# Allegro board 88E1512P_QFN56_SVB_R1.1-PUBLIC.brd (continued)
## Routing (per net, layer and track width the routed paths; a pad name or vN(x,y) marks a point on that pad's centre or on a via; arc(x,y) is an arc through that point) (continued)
U1_VDD_3.3V: length 101.9
  TOP w0.152: C194.1 v1(179.23,141.82) ; v1(148.35,91.44) 148.51,91.61 148.51,91.65 149.89,93.03 155.77,93.03 178.75,116.01 C22.1
  TOP w0.301: U1.36 148.1,91.69 v1(148.35,91.44)
  L3_PWR1 w0.914: 181.19,109.81 TP25.1 ; TP25.1 182.8,111.42 ; TP25.1 182.8,109.81 ; TP25.1 181.19,111.42
  BOTTOM w0.152: v1(179.23,141.82) 179.23,113.37 181.96,110.65
  BOTTOM w0.508: C47.1 v1(151.82,96.2) ; C46.1 v1(151.82,92.11) ; C195.1 181.96,110.65 TP25.1 C196.1 ; C50.1 v1(148.35,91.44) ; C48.1 v1(151.82,93.94) ; C49.1 v1(157.72,91.28)
  BOTTOM w2.032: L18.1 TP25.1
U1_VDDO: length 18.7
  TOP w0.3: U1.49 142.36,94.72 v1(142.54,94.54) ; U1.52 v1(140.86,94.51) ; v1(139.02,89.69) U1.11
  L3_PWR1 w0.914: 100.79,115.02 TP21.1 ; TP21.1 102.41,115.02 ; TP21.1 100.79,116.63 ; TP21.1 102.41,116.63
  BOTTOM w0.508: v1(140.86,94.51) 140.86,95.2 C18.1 ; v1(142.54,94.54) 142.93,94.93 C16.1 ; L13.1 99.6,116.28 C177.1 ; C21.1 139,89.67 v1(139.02,89.69) ; C17.1 v1(134.31,88.94) ; C20.1 v1(131.58,89.06) ; C176.1 TP21.1 ; C19.1 v1(140.83,109.48)
  BOTTOM w2.032: L13.1 TP21.1
U1_XTAL1: length 18.2
  TOP w0.301: U1.34 146.69,90.69 146.8,90.81 148.97,90.81 149.29,91.12 156.4,91.12 159.26,93.98 R3.1 R5.2
U1_XTAL2: length 17.7
  TOP w0.301: U1.33 151.62,90.19 152.43,89.38 162.12,89.38 R6.1
U2_1.8V: length 18.2
  L3_PWR1 w0.914: 78.44,49.61 JP33.1 ; JP33.1 80.05,49.61 ; JP33.1 78.44,51.22 ; JP33.1 80.05,51.22 ; 77.17,31.29 JP31.1 ; JP31.1 78.78,31.29 ; JP31.1 78.78,29.67 ; JP31.1 77.17,29.67 ; JP32.1 73.7,49.61 ; JP32.1 72.09,49.61 ; JP32.1 72.09,51.22 ; JP32.1 73.7,51.22 ; JP34.1 32.17,35.39 ; JP34.1 32.17,37 ; JP34.1 30.56,35.39 ; JP34.1 30.56,37
U2_AVDD_1.8V: length 23.5
  TOP w0.3: v1(55.67,92.69) U2.38 ; 54.85,88.16 v1(55.12,88.42)
  TOP w0.301: 54.85,88.16 54.83,88.13 U2.26 ; U2.19 51.33,88.22 v1(51.15,88.4) ; v1(59.88,93.5) 59.09,93.5 58.77,93.19 U2.39
  L4_PWR2 w0.914: 72.09,60.11 TP18.1 ; TP18.1 72.09,58.5 ; TP18.1 73.7,58.5 ; TP18.1 73.7,60.11
  BOTTOM w0.508: v1(55.67,92.69) 55.65,92.69 55.49,92.84 C81.1 ; C84.1 v1(53.69,77.21) ; v1(55.12,88.42) 55.78,88.42 C83.1 ; C80.1 v1(49.37,82.1) ; C82.1 v1(59.88,93.5) ; C87.1 50.53,87.79 v1(51.15,88.4) ; C86.1 v1(63.36,71.38) ; C171.1 TP18.1 ; C85.1 v1(72.63,82.71)
  BOTTOM w2.032: C170.1 TP18.1 L9.1
U2_AVDD_3.3V: length 18.1
  TOP w0.3: v1(54.17,88.4) 54.33,88.23 U2.25
  TOP w0.301: v1(52.1,88.39) 51.83,88.12 U2.20 51.83,86.63 v1(51.78,86.58) ; v1(54.39,86.58) 54.33,86.65 U2.25
  L3_PWR1 w0.914: TP28.1 31.67,65.62 ; TP28.1 31.67,67.23 ; TP28.1 30.06,65.62 ; TP28.1 30.06,67.23
  BOTTOM w0.508: v1(54.17,88.4) 54.46,88.11 C88.1 ; C91.1 v1(53.86,71.38) ; C208.1 TP28.1 C207.1 ; C90.1 54.37,86.56 v1(54.39,86.58) ; C89.1 51.81,88.1 v1(52.1,88.39) ; v1(51.78,86.58) 51.81,86.56 C92.1
  BOTTOM w2.032: L22.1 TP28.1
U2_AVDDC_1.8V: length 14.6
  TOP w0.3: U2.35 v1(55.65,91.19)
  L3_PWR1 w0.914: TP19.1 80.05,58.5 ; TP19.1 78.44,60.11 ; TP19.1 80.05,60.11 ; TP19.1 78.44,58.5
  BOTTOM w0.508: C78.1 v1(60.21,71.38) ; C77.1 v1(68.19,88.28) ; C76.1 v1(56.57,87.31) ; v1(55.65,91.19) 56.29,91.19 C79.1 ; C172.1 TP19.1
  BOTTOM w2.032: L10.1 TP19.1 C173.1
U2_AVDDF_1.8V: length 16.2
  TOP w0.3: U2.3 v1(49.56,93.69)
  TOP w0.301: U2.3 46.83,93.69 v1(46.82,93.68)
  L4_PWR2 w0.914: TP20.1 32.17,44.28 ; TP20.1 30.56,45.89 ; TP20.1 30.56,44.28 ; TP20.1 32.17,45.89
  BOTTOM w0.508: v1(49.56,93.69) 49.56,93.69 C72.1 ; C174.1 31.4,45.11 TP20.1 C175.1 ; C74.1 v1(47.99,99.43) ; v1(46.82,93.68) 46.2,93.68 C75.1 ; C73.1 v1(40.78,96.53)
  BOTTOM w2.032: L11.1 TP20.1
U2_CLK125: length 42.5
  TOP w0.152: U2.9 29.83,90.69 24.38,96.14 J10.1
  BOTTOM w0.152: C63.1 J10.1
U2_CONFIG: length 61.4
  TOP w0.152: U2.15 49.33,85.01 48.64,84.33 48.64,81.41 37.85,70.61 22.35,70.61 18.29,66.55 18.29,64.52 9.74,55.97 R150.1 7.62,53.85 JP58.1
U2_LED_0: length 68.8
  TOP w0.152: U2.14 46.66,88.19 45.47,87 42.74,87 34.99,79.25 v1(20.95,79.25)
  BOTTOM w0.152: v1(20.95,79.25) 16.38,74.68 16.38,53.09 15.75,52.45 14.22,52.45 12.95,53.72 JP13.5 12.57,52.96 13.84,51.69 R31.2
U2_LED_1: length 68.5
  TOP w0.152: JP13.3 16.38,52.45 21.46,52.45 JP54.1 R164.1 ; v1(32.38,81.28) 35.75,81.28 42.1,87.63 45.34,87.63 46.4,88.69 U2.13
  BOTTOM w0.152: JP54.1 24.38,52.83 24.38,60.71 20.32,64.77 20.32,70.36 31.24,81.28 v1(32.38,81.28)
U2_LED_2: length 57.6
  TOP w0.152: INTN_2.1 JP14.1 ; U2.12 46.04,89.19 45.28,88.42 41.47,88.42 36.61,83.57 v1(26.54,83.57)
  BOTTOM w0.152: INTN_2.1 19.3,61.98 19.3,75.31 26.54,82.55 v1(26.54,83.57)
U2_MDC: length 183.4
  TOP w0.152: v1(47.5,91.95) 47.76,91.69 U2.7 ; v1(138.81,112.52) 138.81,127.13 136.65,129.29 136.65,135.89 140.21,139.45 140.21,181.93 143.95,185.67 v1(145.45,185.67)
  BOTTOM w0.152: v1(47.5,91.95) 47.5,96.01 48.9,97.41 56.64,97.41 58.77,99.54 67.18,99.54 74.33,106.68 104.9,106.68 110.74,112.52 v1(138.81,112.52) ; v1(145.45,185.67) U4.6
U2_MDI_N_0: length 49
  TOP w0.127: R68.1 64.77,43.46 64.77,72.29 56.59,80.47 56.59,82.37 55.36,83.6 55.36,87.46 U2.27
U2_MDI_N_1: length 46.6
  TOP w0.127: U2.23 53.36,87.46 53.36,85.61 53.36,85.6 53.36,83.44 54.96,81.84 54.96,75.11 57.1,72.97 57.1,43.41 R73.1
U2_MDI_N_2: length 46.3
  TOP w0.127: R78.1 49.48,43.41 49.48,73.2 51.35,75.08 51.35,80.69 52.33,81.66 U2.21
U2_MDI_N_3: length 48.6
  TOP w0.127: R83.1 41.86,43.41 41.86,70.92 49.45,78.51 49.45,80.79 50.36,81.71 50.36,87.46 U2.17
U2_MDI_P_0: length 49
  TOP w0.127: R64.1 65.2,43.41 65.2,72.47 57.02,80.65 57.02,82.55 55.79,83.78 55.79,87.46 U2.28
U2_MDI_P_1: length 46.7
  TOP w0.127: R69.1 57.53,43.46 57.53,73.15 55.39,75.29 55.39,82.02 53.79,83.62 53.79,85.6 53.8,85.61 53.8,87.46 U2.24
U2_MDI_P_2: length 46.3
  TOP w0.127: U2.22 52.83,86.74 52.82,86.74 52.82,81.55 51.78,80.51 51.78,74.9 49.91,73.03 49.91,43.46 R74.1
U2_MDI_P_3: length 48.6
  TOP w0.127: U2.18 50.79,87.46 50.79,81.53 49.88,80.61 49.88,78.33 42.29,70.74 42.29,43.47 R80.2
U2_RESETN: length 137.7
  TOP w0.152: JP3.2 69.85,180.47 69.85,177.67 62.48,170.31 56.01,170.31 30.99,145.29 v1(30.99,129.79) ; v1(49.4,83.82) 49.83,84.24 U2.16
  BOTTOM w0.152: v1(30.99,129.79) 30.99,112.27 33.53,109.73 33.53,90.65 41.62,82.55 47.82,82.55 49.09,83.82 v1(49.4,83.82) ; R2.2 JP3.2
U2_RX_CLK: length 32.1
  TOP w0.152: v1(55.12,102.87) 54.33,102.08 U2.46 ; v1(55.12,106.68) 55.12,111.12 58.55,114.55 58.55,116.71 52.93,122.33 R139.1 R141.2
  BOTTOM w0.152: v1(55.12,106.68) v1(55.12,102.87)
U2_RX_CLK1: length 2.4
  TOP w0.152: R141.1 JP24.12
U2_RX_CTRL: length 33.8
  TOP w0.152: U2.43 55.83,99.9 60.96,105.03 60.96,108.46 69.6,117.09 JP24.2
U2_RXD_0: length 32.9
  TOP w0.152: JP24.4 67.06,116.59 59.94,109.47 59.94,105.16 55.33,100.54 U2.44
U2_RXD_1: length 32.1
  TOP w0.152: JP24.6 64.52,115.57 58.93,109.98 58.93,105.41 54.83,101.31 U2.45
U2_RXD_2: length 32.5
  TOP w0.152: U2.47 53.83,102.85 58.17,107.19 58.17,111 63.25,116.08 63.25,122.17 JP24.8
U2_RXD_3: length 32.6
  TOP w0.152: JP24.10 61.85,121.03 61.85,115.95 56.9,111 56.9,107.19 53.33,103.62 U2.48
U2_SIN_N: length 75.6
  TOP w0.127: C147.1 15.59,148.6 15.59,145.57 26.87,134.29 26.87,105.36 37.97,94.26 48.56,94.26 U2.2
U2_SIN_P: length 74.8
  TOP w0.127: U2.1 38.15,94.69 27.3,105.54 27.3,134.47 16.02,145.75 16.02,148.7 R98.2
U2_SOUT_N: length 45.3
  TOP w0.127: C154.2 15.35,113.53 15.35,109.77 32.46,92.66 48.6,92.66 U2.5
U2_SOUT_P: length 44.7
  TOP w0.127: R107.2 15.78,113.4 15.78,109.95 32.64,93.09 48.53,93.09 U2.4
U2_TX_CLK: length 40.6
  TOP w0.152: v1(50.99,100.95) 50.83,100.79 U2.53 ; R137.1 R143.2 35.47,124.88 JP53.11 37.85,124.71 37.85,114.68 47.5,105.03 v1(47.5,102.87)
  BOTTOM w0.152: v1(50.99,100.95) 50.98,100.96 49.41,100.96 v1(47.5,102.87)
U2_TX_CLK1: length 125.3
  TOP w0.152: R143.1 34.04,120.14 v1(36.83,117.35) ; v1(73.53,124.46) v1(73.53,120.65)
  BOTTOM w0.152: v1(36.83,117.35) 38.61,117.35 40.26,115.7 68.58,115.7 v1(73.53,120.65) ; JP23.12 140.84,130.43 137.41,127 116.97,127 112.65,131.32 91.95,131.32 87.63,127 76.07,127 v1(73.53,124.46)
U2_TX_CTRL: length 161.1
  TOP w0.152: U2.56 49.33,96.09 48.77,96.65 v1(48.77,102.87) ; v1(53.21,105.25) 53.21,110.49 54.99,112.27 54.99,117.09 50.55,121.54 50.55,124.71 JP53.1
  BOTTOM w0.152: JP23.2 153.54,124.59 152.78,123.83 115.44,123.83 111.12,128.14 94.23,128.14 89.92,123.83 72.14,123.83 68.2,119.89 53.59,119.89 52.7,120.78 52.7,126.11 51.82,127 49.66,127 49.28,126.62 JP53.1 ; v1(53.21,105.25) 52.9,104.93 50.83,104.93 v1(48.77,102.87)
U2_TXD_0: length 160.7
  TOP w0.152: v1(78.61,124.46) 78.61,122.87 v1(78.62,122.86) ; JP53.3 48.01,124.71 48.01,118.49 49.28,117.22 52.58,117.22 54.1,115.7 54.1,112.78 52.58,111.25 52.58,96.39 52.33,96.14 U2.50
  BOTTOM w0.152: JP23.4 151,125.6 149.86,124.46 115.8,124.46 111.48,128.78 93.85,128.78 89.53,124.46 v1(78.61,124.46) ; v1(78.62,122.86) 78.16,123.32 72.52,123.32 67.82,118.62 52.2,118.62 51.43,119.38 51.43,124.21 50.93,124.71 48.01,124.71 JP53.3
U2_TXD_1: length 159.9
  TOP w0.152: v1(77.34,124.46) v1(77.34,122.56) ; U2.51 51.83,114.92 50.55,116.2 47.12,116.2 45.47,117.86 45.47,124.71 JP53.5
  BOTTOM w0.152: JP23.6 148.46,127.64 145.92,125.09 116.2,125.09 111.89,129.41 93.47,129.41 89.15,125.09 77.98,125.09 v1(77.34,124.46) ; v1(77.34,122.56) 72.77,122.56 67.95,117.73 46.99,117.73 45.47,119.25 45.47,124.71 JP53.5
U2_TXD_2: length 161.2
  TOP w0.152: U2.54 50.33,96.87 50.04,97.16 50.04,99.69 50.04,112.4 47.88,114.55 43.81,114.55 42.93,115.44 42.93,124.71 JP53.7 ; v1(76.07,124.46) v1(76.07,121.92)
  BOTTOM w0.152: v1(76.07,124.46) 77.34,125.73 88.65,125.73 92.96,130.05 112.01,130.05 116.33,125.73 143,125.73 145.92,128.65 JP23.8 ; v1(76.07,121.92) 73.02,121.92 68.07,116.97 45.09,116.97 42.93,119.13 42.93,124.71 JP53.7
U2_TXD_3: length 162.6
  TOP w0.152: U2.55 49.83,96.48 49.4,96.9 49.4,108.59 47.62,110.36 43.56,110.36 40.39,113.54 40.39,124.71 JP53.9 ; v1(74.8,124.46) v1(74.8,121.29)
  BOTTOM w0.152: JP53.9 40.39,124.71 40.39,119.13 43.31,116.2 68.07,116.2 73.15,121.29 v1(74.8,121.29) ; JP23.10 143.38,129.41 140.34,126.37 116.71,126.37 112.39,130.68 92.58,130.68 88.27,126.37 76.71,126.37 v1(74.8,124.46)
U2_V18: length 24.7
  TOP w0.152: JP8.1 44.96,88.9 46.25,90.19 U2.10
  BOTTOM w0.152: R24.2 JP8.1
U2_VDD_1.0V: length 19.2
  TOP w0.3: U2.40 v1(55.65,93.69) ; U2.6 v1(49.46,92.19)
  TOP w0.301: v1(57.78,94.87) 57.61,94.69 U2.42
  TOP w2.032: L17.1 TP24.1
  L4_PWR2 w0.914: TP24.1 50.97,148.38 ; TP24.1 49.36,146.77 ; TP24.1 49.36,148.38 ; TP24.1 50.97,146.77
  BOTTOM w0.508: C64.1 55.81,93.53 v1(55.65,93.69) ; C58.1 49.44,92.21 v1(49.46,92.19) ; C60.1 v1(45.34,108.48) ; C62.1 v1(73.27,104.09) ; C191.1 TP24.1 50.14,147.6 C193.1 ; C61.1 v1(68.19,98.58) ; C59.1 v1(57.78,94.87)
U2_VDD_3.3V: length 17.9
  TOP w0.301: U2.36 59.56,91.69 v1(59.82,91.95)
  L3_PWR1 w0.914: 74.51,110.19 TP26.1 ; TP26.1 74.51,111.8 ; TP26.1 76.12,110.19 ; TP26.1 76.12,111.8
  BOTTOM w0.508: C95.1 v1(64.19,92.43) ; C197.1 77.19,110.8 L19.1 ; C96.1 v1(68.19,92.87) ; C93.1 v1(59.82,91.95) ; C198.1 TP26.1 ; C97.1 v1(64.19,95.85) ; C94.1 v1(61.02,95.85)
  BOTTOM w2.032: L19.1 TP26.1
U2_VDDO: length 17.6
  TOP w0.3: v1(49.51,89.69) U2.11
  TOP w0.301: U2.49 v1(52.83,94.51) ; U2.52 v1(51.33,94.51)
  L3_PWR1 w0.914: TP22.1 29.76,107.49 ; TP22.1 28.15,105.87 ; TP22.1 29.76,105.87 ; TP22.1 28.15,107.49
  BOTTOM w0.508: v1(52.83,94.51) 52.92,94.6 C65.1 ; C66.1 51.28,94.55 v1(51.33,94.51) ; C68.1 v1(42.93,108.43) ; C70.1 v1(44.8,89.69) ; C67.1 49.38,89.56 v1(49.51,89.69) ; C69.1 v1(39.98,89.86) ; C184.1 TP22.1
  BOTTOM w2.032: C182.1 TP22.1 L14.1
U2_XTAL1: length 16.9
  TOP w0.301: U2.34 57.28,90.69 57.63,91.04
  TOP w0.381: 57.63,91.04 72.97,91.04 R17.1
U2_XTAL2: length 18.3
  TOP w0.301: 62.73,90.19 U2.33
  TOP w0.508: 62.73,90.19 63.26,89.66 64.14,89.66 68.71,85.09 R21.1
N16787604: length 2.8
  TOP w0.152: D3.2 96.04,33.26 v1(96.04,34.29)
  BOTTOM w0.152: R30.1 97.15,35.4 v1(96.04,34.29)
N16796830: length 9.3
  TOP w0.152: 181.86,101.98 181.68,101.79 Y1.1
N16796833: length 5.4
  TOP w0.152: Y1.3 164.93,97.6 R4.1
N16796834: length 31.5
  TOP w0.152: R3.2 176.4,93.98 179.71,97.28 183.26,97.28 186.94,100.97 J1.1
  BOTTOM w0.508: C3.1 J1.1
N16796839: length 5.9
  TOP w0.152: C6.1 167.3,92.11 Y2.2 166.69,92.39 R5.1
N16994346: length 40.2
  TOP w0.127: U1.32 146.1,89.66 150.5,89.66 152.05,88.11 155.74,88.11 170.31,73.53 176.43,73.53 v1(177.19,74.29) R10.2
  BOTTOM w0.127: v1(177.19,74.29) 177.03,74.14 R14.1
N16994348: length 40.2
  TOP w0.127: R12.2 v1(177.2,72.39) 176.49,73.1 170.14,73.1 170.01,73.23 155.56,87.67 151.87,87.67 150.32,89.22 146.1,89.22 U1.31
  BOTTOM w0.127: v1(177.2,72.39) 177.04,72.55 R15.1
N17016825: length 19.6
  TOP w0.152: J8.1 87.88,89.66 85.47,92.08 76.08,92.08 R17.2
  BOTTOM w0.508: C54.1 J8.1
N17016957: length 4.5
  TOP w0.152: Y3.3 76.07,95.57 73.69,93.19 73.69,92.87 R18.1
N17016970: length 6.7
  TOP w0.381: Y4.2 74.17,88.27 73.22,89.21 R19.1
  BOTTOM w0.508: Y4.2 78.14,88.43 C55.1
N17016978: length 5.2
  TOP w0.381: R21.2 v1(76.71,85.09)
  BOTTOM w0.381: v1(76.71,85.09) 77.65,85.09 C56.1
  BOTTOM w0.508: R20.1 79.26,84.93 C56.1
N17193751: length 4.8
  TOP w0.152: JP2.3 63.82,184.97 U3.2
N17251537: length 10.2
  TOP w0.152: JP58.2 JP13.8 JP13.6 JP13.4 JP13.2
N17251820: length 3.6
  TOP w0.152: v1(17.97,47.84) 17.02,46.89 D6.2
  BOTTOM w0.152: R33.1 v1(17.97,47.84)
N17493866: length 3.8
  TOP w0.127: JP5.2 181.64,73.18 180.54,73.18 R12.1
N17495532: length 3.7
  TOP w0.127: R11.1 180.38,73.66 181.8,73.66 JP5.1
N17503153: length 3.8
  TOP w0.152: JP7.1 81.03,100.02 Y3.1
N17787307: length 6.3
  TOP w0.152: JP2.2 JP3.1 JP3.3
N17830081: length 10.2
  TOP w0.152: JP57.2 JP11.8 JP11.6 JP11.4 JP11.2
N17893687: length 20.7
  TOP w0.127: U6.11 56.07,26.43 56.07,26.65 55.12,27.6 55.12,29.21 62.92,37.01 62.92,37.03 65.18,39.29 65.18,40.37 R65.1
N17893693: length 20.5
  TOP w0.127: R67.1 64.74,40.37 64.74,39.47 62.49,37.21 62.49,37.19 54.69,29.39 54.69,27.42 55.44,26.67 55.44,26.17 U6.10
N17893695: length 23
  TOP w0.127: R70.1 58.29,41.17 58.06,41.4 57.91,41.4 57.56,41.05 57.56,34.66 53.59,30.7 53.59,24.8 53.61,24.79 53.61,24.69
  TOP w0.152: U6.4 54.18,22.73 54.61,22.73 54.86,22.99 54.86,24.32 54.74,24.45 53.85,24.45 53.61,24.69
N17893699: length 20.1
  TOP w0.127: U6.3 51.31,23.57 51.31,23.97 52.45,25.11 52.45,36.83 49.94,39.34 49.94,40.38 50.67,41.11 R75.1
N17893703: length 20.3
  TOP w0.127: R77.1 49.5,40.37 49.5,39.17 52.02,36.65 52.02,25.29 50.88,24.15 50.87,24.15 U6.2
N17893707: length 22.5
  TOP w0.127: R80.1 43.05,41.11 42.32,40.38 42.32,38.46 49.43,31.34 49.43,29.74
  TOP w0.152: U6.8 48.51,25.86 48.51,26.54 48.8,26.83 50.83,26.83 51.18,27.18 51.18,28.96 50.77,29.37 49.8,29.37 49.43,29.74
N17893711: length 23.6
  TOP w0.127: R82.1 41.88,40.37 41.88,38.28 49,31.16 49,29.76
  TOP w0.152: U6.9 49.71,24.51 48.26,24.51 47.75,25.02 47.75,26.83 47.97,27.05 47.97,28.74 48.13,28.89 48.13,28.89 49,29.76
N18175709: length 24.2
  TOP w0.127: R72.1 57.12,40.37 57.12,34.84 53.16,30.88 53.16,24.61
  TOP w0.152: U6.5 54.88,22.07 53.37,22.07 52.87,22.57 52.87,24.31 53.16,24.61
N18237123: length 4.4
  TOP w0.152: U1.30 v1(149.52,88.69)
  BOTTOM w0.152: R13.1 149.47,88.75 v1(149.52,88.69)
N18290180: length 8.4
  BOTTOM w0.127: R48.2 139.45,47.5 139.45,49.38 138.06,50.76 137.33,50.76 137.03,51.05 JP17.1 136.56,51.35 R50.1
N18290184: length 7.7
  BOTTOM w0.127: R53.2 139.01,47.61 139.01,49.2 137.88,50.33 137.33,50.33 137.03,50.04 JP17.2 136.56,49.75 R50.2
N18290198: length 10.7
  BOTTOM w0.127: U5.2 136.27,36.93 136.69,37.34 136.69,40.28 135.43,41.54 133.5,41.54 132.59,42.45 132.59,43.08 R57.1
N18290204: length 10.7
  BOTTOM w0.127: U5.3 137.54,36.86 137.12,37.28 137.12,40.46 135.6,41.97 133.67,41.97 133.02,42.63 133.02,43.03 R55.1
N18290208: length 8.5
  BOTTOM w0.127: R51.1 138.94,43.08 138.94,42.16 140.5,40.59 140.5,37.31 140.08,36.89 U5.5
N18290216: length 8.6
  BOTTOM w0.127: R49.1 139.37,43.03 139.37,42.34 140.93,40.77 140.93,37.28 141.35,36.86 141.35,36.26
N18290228: length 8.3
  BOTTOM w0.127: U5.8 143.89,36.89 144.31,37.31 144.31,41.29 145.33,42.31 145.33,43.03 R45.1
N18290246: length 8.4
  BOTTOM w0.127: R56.1 130.21,51.35 JP18.1 130.68,51.05 130.98,50.76 131.71,50.76 133.1,49.38 133.1,47.5 R54.2
N18290250: length 7.7
  BOTTOM w0.127: R56.2 130.21,49.75 JP18.2 130.68,50.04 130.98,50.33 131.53,50.33 132.66,49.2 132.66,47.61 R59.2
N18290323: length 8.3
  BOTTOM w0.127: U5.9 145.16,36.86 144.74,37.28 144.74,41.11 145.76,42.13 145.76,43.08 R43.1
N18290640: length 8.3
  BOTTOM w0.127: R37.1 149.26,51.35 JP15.1 149.73,51.02 150.05,50.7 150.66,50.7 152.15,49.22 152.15,47.5 R40.2
N18290658: length 7.5
  BOTTOM w0.127: R42.2 151.71,47.61 151.71,49.04 150.48,50.27 150.09,50.27 149.73,49.91 JP15.2 149.26,49.75 R37.2
N18290664: length 8.5
  BOTTOM w0.127: 146.51,15.42 148.12,17.03 148.12,21.23 U5.14
  BOTTOM w0.152: 145.29,15.88 145.74,15.42 146.51,15.42
N18290670: length 9.3
  BOTTOM w0.127: 148.97,21.65 148.55,21.23 148.55,16.85 146.56,14.86
  BOTTOM w0.152: 146.56,14.86 CON1.1
N18290676: length 9.1
  TOP w0.127: v1(145.13,18.16) 144.81,17.84 144.81,17.18 144.02,16.38
  TOP w0.152: CON1.3 144.02,16.38
  BOTTOM w0.127: U5.16 144.81,21.3 144.81,18.48 v1(145.13,18.16)
N18290682: length 9.5
  TOP w0.127: v1(144.02,18.16) 144.38,17.8 144.38,17.36 143.98,16.95
  TOP w0.152: 140.21,15.88 141.29,16.95 143.98,16.95
  BOTTOM w0.127: v1(144.02,18.16) 144.34,18.48 144.34,21.21 U5.17
N18290688: length 9.3
  BOTTOM w0.127: 141.95,14.64 141.75,14.84 141.75,18.78 140.97,19.56 140.97,21.27 141.35,21.65
  BOTTOM w0.152: 142.75,15.88 142.75,15.11 142.27,14.64 141.95,14.64
N18290694: length 8.9
  BOTTOM w0.127: 141.48,14.48 141.32,14.64 141.32,18.6 140.54,19.38 140.54,21.2 U5.20
  BOTTOM w0.152: 141.48,14.48 CON1.5
N18290700: length 9.5
  BOTTOM w0.127: 138.94,14.32 138.94,14.48 139.19,14.73 139.19,17.78 137.12,19.85 137.12,21.23 U5.22
  BOTTOM w0.152: CON1.7 138.94,14.32
N18290706: length 10
  BOTTOM w0.127: U5.23 136.69,21.23 136.69,19.67 138.76,17.6 138.76,14.91 138.49,14.64
  BOTTOM w0.152: 138.49,14.64 137.99,14.64 137.67,14.95 137.67,15.88
N18290712: length 1.8
  BOTTOM w0.762: C105.1 R38.1
N18290718: length 20.7
  TOP w0.762: R52.2 124.19,22.12 C118.1
  BOTTOM w0.762: R52.2 127.51,25.15 136.78,25.15 138.81,23.11 U5.21
N18290720: length 10.5
  TOP w0.762: C120.1 128.29,22.12 R58.2
  BOTTOM w0.762: R58.2 129.29,23.11 133.54,23.11 U5.24
N18290726: length 14.7
  TOP w0.762: R38.2 153.69,21.97 C100.1
  BOTTOM w0.762: U5.15 146.43,22.86 147.45,23.88 154.18,23.88 R38.2
N18290728: length 1.8
  BOTTOM w0.762: C109.1 R46.1
N18290732: length 1.8
  BOTTOM w0.762: C113.1 R52.1
N18290736: length 24.1
  TOP w0.762: R46.2 162.29,21.97 C98.1
  BOTTOM w0.762: U5.18 142.62,23.24 145.16,25.78 156.08,25.78 R46.2
N18290738: length 1.8
  BOTTOM w0.762: C117.1 R58.1
N18290828: length 9.4
  BOTTOM w0.127: R36.1 152.07,43.03 152.07,41.61 148.55,38.09 148.55,37.28 148.97,36.86 148.97,36.26
N18290888: length 8.4
  BOTTOM w0.127: R39.2 146.09,47.21 146.08,47.21 145.74,47.55 145.74,49.43 144.41,50.76 143.7,50.76 143.38,51.08 JP16.1 142.91,51.35 R44.1
N18290892: length 7.6
  BOTTOM w0.127: R44.2 142.91,49.75 JP16.2 143.38,49.91 143.8,50.33 144.23,50.33 145.31,49.25 145.31,47.56 R47.2
N18290908: length 9.3
  BOTTOM w0.127: U5.11 147.7,36.89 148.12,37.31 148.12,38.27 151.64,41.79 151.64,43.08 R41.1
N18307922: length 12.1
  TOP w0.127: R64.2 v1(67.51,43.65)
  BOTTOM w0.127: R66.1 61,48.42 JP19.1 62.52,47.84 63.29,47.84 65.12,46.01 65.12,43.97
  BOTTOM w0.152: 65.12,43.97 65.44,43.65 v1(67.51,43.65)
N18307926: length 11.3
  TOP w0.127: R68.2 v1(62.41,43.65)
  BOTTOM w0.127: R66.2 61,46.83 JP19.2 62.52,47.41 63.11,47.41 64.69,45.83 64.69,44.02
  BOTTOM w0.152: v1(62.41,43.65) 64.32,43.65 64.69,44.02
N18317435: length 12.1
  TOP w0.127: R69.2 v1(59.89,43.65)
  BOTTOM w0.127: 57.5,43.97 57.5,46.01 55.67,47.84 54.9,47.84 JP20.1 53.38,48.42 R71.1
  BOTTOM w0.152: 57.5,43.97 57.82,43.65 v1(59.89,43.65)
N18317437: length 11.3
  TOP w0.127: R73.2 v1(54.79,43.65)
  BOTTOM w0.127: R71.2 53.38,46.83 JP20.2 54.9,47.41 55.49,47.41 57.07,45.83 57.07,44.02
  BOTTOM w0.152: v1(54.79,43.65) 56.7,43.65 57.07,44.02
N18317956: length 12.1
  TOP w0.127: R74.2 v1(52.27,43.65)
  BOTTOM w0.127: R76.1 45.76,48.42 JP21.1 47.28,47.84 48.05,47.84 49.88,46.01 49.88,43.97
  BOTTOM w0.152: 49.88,43.97 50.2,43.65 v1(52.27,43.65)
N18317958: length 11.3
  TOP w0.127: R78.2 v1(47.17,43.65)
  BOTTOM w0.127: R76.2 45.76,46.83 JP21.2 47.28,47.41 47.87,47.41 49.45,45.83 49.45,44.02
  BOTTOM w0.152: v1(47.17,43.65) 49.08,43.65 49.45,44.02
N18318493: length 12.1
  TOP w0.152: R79.2 v1(44.65,43.65)
  BOTTOM w0.127: R81.1 38.14,48.42 JP22.1 39.66,47.84 40.43,47.84 42.26,46.01 42.26,43.97
  BOTTOM w0.152: 42.26,43.97 42.58,43.65 v1(44.65,43.65)
N18318495: length 11.3
  TOP w0.152: R83.2 v1(39.55,43.65)
  BOTTOM w0.127: 41.83,44.02 41.83,45.83 40.25,47.41 39.66,47.41 JP22.2 38.14,46.83 R81.2
  BOTTOM w0.152: v1(39.55,43.65) 41.46,43.65 41.83,44.02
N18570142: length 2.3
  BOTTOM w0.152: JP12.2 97.16,37.47 R30.2
N18601588: length 51.7
  TOP w0.152: U1.29 146.1,88.16 149.46,88.16 150.88,86.74 153.42,86.74 167.64,72.52 167.64,57.66 JP6.1
N18793953: length 5.5
  TOP w0.152: C7.1 167.14,86.86 Y2.1 167.09,86.83 R6.2
N19074906: length 29.6
  TOP w0.152: JP10.1 72.9,75.18 72.9,76.36 61.47,87.79 58.13,87.79 57.73,88.19 U2.29
N19074920: length 4.6
  TOP w0.152: v1(60.04,88.69) U2.30
  BOTTOM w0.152: v1(60.04,88.69) 59.98,88.75 R25.1
N19074934: length 29.1
  TOP w0.127: U2.31 56.56,89.22 61.4,89.22 75.02,75.6 76.92,75.6 77.98,74.55
  BOTTOM w0.127: R27.1 77.98,74.55
N19074982: length 29.1
  TOP w0.127: U2.32 56.56,89.66 61.58,89.66 75.2,76.03 76.92,76.03 JP9.2
  BOTTOM w0.127: R26.1 JP9.2
N19224300: length 22.8
  L4_PWR2 w0.914: 169.25,162.39 JP49.2 ; JP49.2 170.86,162.39 ; JP49.2 169.25,164 ; JP49.2 170.86,164 ; 83.4,110.19 JP48.1 ; JP48.1 85.01,110.19 ; JP48.1 83.4,111.8 ; JP48.1 85.01,111.8 ; JP52.1 22.78,67.23 ; JP52.1 21.17,65.62 ; JP52.1 22.78,65.62 ; JP52.1 21.17,67.23 ; JP47.1 191.69,109.81 ; JP47.1 190.08,111.42 ; JP47.1 190.08,109.81 ; JP47.1 191.69,111.42 ; JP50.1 90.34,62.06 ; JP50.1 88.73,62.06 ; JP50.1 90.34,63.67 ; JP50.1 88.73,63.67
N19224537: length 2.3
  BOTTOM w2.032: L21.2 JP50.2
N19224649: length 6.2
  TOP w0.254: C201.1 179.91,175.78 U12.9 178.68,175.78 178.38,176.08 178.38,176.38 177.48,177.28 U12.1
  TOP w0.508: R135.2 181.19,176.08 C201.1
N19224675: length 1.5
  TOP w0.152: R126.1 113.32,179.32 U11.14
N19224683: length 6.2
  TOP w0.254: U11.1 115.33,178.05 115.85,178.57 115.85,179.5 116.12,179.78 116.51,179.78 116.83,180.1 U11.9 116.83,181.31 C189.1
  TOP w0.508: C189.1 116.53,182.58 R130.2
N19224747: length 3.6
  TOP w0.152: R128.1 112.42,178.44 113.86,178.44 114.24,178.82 U11.15
N19224753: length 3.6
  TOP w2.032: L15.2 JP43.2
N19224758: length 13.7
  L3_PWR1 w0.914: JP44.2 126.41,167.47 ; JP44.2 124.8,169.08 ; JP44.2 126.41,169.08 ; JP44.2 124.8,167.47 ; JP45.1 50.97,156.93 ; JP45.1 50.97,158.54 ; JP45.1 49.36,156.93 ; JP45.1 49.36,158.54 ; JP43.1 137.08,165.56 ; JP43.1 135.47,165.56 ; JP43.1 135.47,167.18 ; JP43.1 137.08,167.18
N19224792: length 1.7
  TOP w0.508: D11.1 R131.2
N19224808: length 1.5
  TOP w0.152: U12.14 177.92,179.29 R132.2
N19224958: length 1.7
  BOTTOM w2.032: L22.2 JP52.2
N19224996: length 3.6
  TOP w0.152: U12.15 177.42,178.37 177.04,178.75 177.04,180.19 R133.1
N19225038: length 2.3
  TOP w2.032: L17.2 JP45.2
N19225131: length 1.8
  TOP w0.152: D10.1 R125.2
N19227820: length 13.5
  L3_PWR1 w0.914: JP41.1 29.76,116.38 ; JP41.1 28.15,116.38 ; JP41.1 29.76,114.76 ; JP41.1 28.15,114.76 ; 142.58,167.18 JP39.2 ; JP39.2 142.58,165.56 ; JP39.2 143.38,167.44 ; JP39.2 143.38,165.3 ; 92.16,116.63 JP40.1 ; JP40.1 93.77,115.02 ; JP40.1 93.77,116.63 ; JP40.1 92.16,115.02
N19228113: length 1.7
  BOTTOM w2.032: L6.2 JP26.2
N19228203: length 1.5
  TOP w0.152: U9.14 18.81,19.93 R113.2
N19228291: length 6.6
  TOP w0.152: C167.1 16.07,23.14
  TOP w0.254: C167.1 17.02,23.14 17.32,23.44 U9.9 18.12,23.44 18.36,23.19 18.36,22.89 19.31,21.94 U9.1
  TOP w0.381: C167.1 15.55,23.14 R116.2
N19228315: length 1.7
  BOTTOM w2.032: L5.2 JP25.2
N19228347: length 10.4
  TOP w0.254: U9.3 20.94,22.94 21.15,22.73 21.15,22.73 v1(21.62,22.26)
  BOTTOM w0.508: v1(25.91,27.18) 25.91,25.75 22.41,22.26 v1(21.62,22.26) ; R112.1 JP29.2
N19228371: length 23.7
  TOP w0.152: v1(157.67,176.85) 157.67,176.69 157.6,176.62 U10.14
  BOTTOM w0.508: v1(157.67,176.85) 160.53,176.85 163.39,179.7 163.39,185.1 JP35.2 JP36.2 JP37.2 JP38.2
N19228441: length 1.7
  TOP w0.508: D8.1 R110.2
N19228445: length 1.7
  TOP w0.152: D9.1 v1(160.21,163.83)
  BOTTOM w0.152: R117.2 v1(160.21,163.83)
N19228523: length 3.6
  TOP w0.152: U9.15 19.31,20.85 19.7,20.46 19.7,19.03 R114.1
N19228594: length 1.7
  BOTTOM w2.032: L8.2 JP28.2
N19228794: length 1.7
  BOTTOM w2.032: L14.2 JP41.2
N19228818: length 1.5
  BOTTOM w2.032: L13.2 JP40.2
N19228838: length 6.2
  TOP w0.254: C180.1 159.59,173.24 U10.9 158.36,173.24 158.06,173.54 158.06,173.84 157.16,174.74 U10.1
  TOP w0.508: C180.1 160.87,173.54 R123.2
N19228887: length 3.6
  TOP w0.152: R118.1 156.72,177.65 156.72,176.21 157.1,175.83 U10.15
N19228961: length 13.7
  L4_PWR2 w0.914: JP27.2 125.52,29.76 ; JP27.2 123.91,29.76 ; JP27.2 125.52,28.15 ; JP27.2 123.91,28.15 ; 29.55,28.28 JP29.1 ; JP29.1 29.55,29.89 ; JP29.1 31.16,28.28 ; JP29.1 31.16,29.89 ; JP31.2 78.78,28.75 ; JP31.2 78.78,27.13 ; JP31.2 77.17,28.75 ; JP31.2 77.17,27.13
N19229117: length 1.7
  BOTTOM w2.032: L10.2 79.25,52.96
N19229193: length 1.7
  BOTTOM w2.032: L9.2 72.9,52.96
N19229239: length 1.7
  BOTTOM w2.032: L11.2 JP34.2
N19229269: length 1.7
  BOTTOM w0.508: R120.1 JP36.1
N19229277: length 22
  TOP w2.54: F1.1 J20.1 J20.2
  BOTTOM w0.508: C159.1 J20.1
  BOTTOM w1.016: C160.1 163.96,200.45 J20.2
N19229287: length 2.6
  TOP w0.508: D7.1 152.53,197.4 v1(152.53,196.06)
  BOTTOM w0.508: R111.1 v1(152.53,196.06)
N19241861: length 4.4
  TOP w0.508: U7.15 v1(88.57,168.81)
  BOTTOM w0.508: C142.1 88.57,169.43 v1(88.57,168.81) 88.57,168.23 88.05,167.71 L2.1
N19242097: length 16.9
  TOP w0.152: C145.1 79.09,156.84 79.09,161.77 77.03,163.83 J14.1
N19242099: length 16.8
  TOP w0.152: J13.1 64.01,163.83 67.18,160.66 67.18,156.36 C144.1
N19242143: length 6.7
  TOP w0.508: U7.16 v1(89.37,168.81)
  BOTTOM w0.508: C138.1 89.72,171.73 C139.1 89.37,169.52 v1(89.37,168.81) 89.37,168.24 89.81,167.8 L1.2
N19242271: length 9.2
  TOP w0.152: C136.2 98.3,150.81 J11.1
N19242275: length 10.1
  TOP w0.152: J12.1 85.6,152.87 C137.2
N19242333: length 31.7
  TOP w0.127: U7.18 91.16,167.17 91.16,163.35 91.95,162.56 92.88,162.56 v1(93.22,162.22) ; R94.1 73.53,155.42 v1(73.53,155.89)
  BOTTOM w0.127: v1(73.53,155.89) 73.17,156.25 73.17,157.28 75.91,160.02 88.11,160.02 90.65,162.56 92.88,162.56 v1(93.22,162.22)
N19242335: length 31.8
  TOP w0.127: R95.1 72.27,155.43 72.27,155.79 72.18,155.88 v1(72.18,155.88) ; v1(93.22,163.33) 92.88,162.99 92.13,162.99 91.59,163.53 91.59,167.17 U7.19
  BOTTOM w0.127: v1(93.22,163.33) 92.88,162.99 90.47,162.99 87.93,160.45 75.74,160.45 72.74,157.46 72.74,156.44 v1(72.18,155.88)
N19242343: length 20.7
  TOP w0.127: U7.13 86.76,167.13 86.76,164.55 93.2,158.11 93.2,150.52 94.01,149.71 R85.1
N19242345: length 20.7
  TOP w0.127: R86.1 92.76,150.52 92.76,157.93 86.32,164.37 86.32,167.2 U7.12
N19242395: length 2.9
  TOP w0.152: U7.6 v1(88.17,177.01)
  BOTTOM w0.152: R89.1 87.82,177.64 87.82,177.36 v1(88.17,177.01)
N19242397: length 2.6
  TOP w0.152: U7.5 v1(88.97,177.01)
  BOTTOM w0.152: R90.1 88.97,178.07 v1(88.97,177.01)
N19242401: length 2.9
  TOP w0.152: U7.4 v1(89.77,177.01)
  BOTTOM w0.152: R91.1 90.04,177.64 90.04,177.28 v1(89.77,177.01)
N19242403: length 2.9
  TOP w0.152: U7.2 v1(91.37,177.07)
  BOTTOM w0.152: R92.1 92.1,178.11 91.63,177.64 91.63,177.32 v1(91.37,177.07)
N19242417: length 3
  TOP w0.152: U7.8 v1(86.57,177.01)
  BOTTOM w0.152: v1(86.57,177.01) 86.39,177.19 86.39,177.64 85.92,178.11 R88.1
N19251259: length 4.6
  TOP w0.508: U8.15 v1(30.15,168.81)
  BOTTOM w0.508: L4.1 29.63,167.8 30.15,168.32 v1(30.15,168.81) 30.15,169.59 C152.1
N19251492: length 8.2
  TOP w0.152: C155.1 21.97,118.01 J18.1
N19251494: length 8.2
  TOP w0.152: J17.1 9.27,118.01 12.92,114.37 C154.1
N19251531: length 6.7
  TOP w0.508: U8.16 v1(30.95,168.81)
  BOTTOM w0.508: C148.1 31.46,172.05 C149.1 31.38,170.02 30.95,169.59 v1(30.95,168.81) 30.95,168.27 31.39,167.83 L3.2
N19251660: length 8.2
  TOP w0.152: C146.2 22.1,153.19 J15.1
N19251670: length 8.1
  TOP w0.152: C147.2 9.4,153.51 J16.1
N19251724: length 70.6
  TOP w0.127: v1(32.44,163.47) 32.74,163.76 32.74,166.37 32.55,166.55 U8.18 ; R107.1 15.84,116.85 15.84,142.02 12.17,145.69 11.16,145.69 v1(10.83,146.02)
  BOTTOM w0.127: v1(10.83,146.02) 11.16,145.69 11.76,145.69 12.57,146.5 12.57,151.76 22.53,161.72 32.24,161.72 32.78,162.26 32.78,163.13 v1(32.44,163.47)
N19251726: length 70.7
  TOP w0.127: v1(10.83,144.92) 11.16,145.26 11.99,145.26 15.41,141.85 15.41,116.69 14.67,115.96 R108.1 ; U8.19 33.35,166.71 33.17,166.53 33.17,163.85 v1(33.55,163.47)
  BOTTOM w0.127: v1(33.55,163.47) 33.21,163.13 33.21,162.08 32.42,161.29 22.71,161.29 13,151.59 13,146.32 11.94,145.26 11.16,145.26 v1(10.83,144.92)
N19251738: length 25.5
  TOP w0.127: R98.1 15.96,152.03 15.96,158.17 19.4,161.61 25.75,161.61 28.37,164.23 28.37,166.53 28.55,166.71 U8.13
N19251740: length 25.5
  TOP w0.127: R99.1 15.53,152.03 15.53,158.35 19.22,162.04 25.57,162.04 27.94,164.41 27.94,166.53 27.75,166.71 U8.12
N19251790: length 2.9
  TOP w0.152: U8.6 v1(29.75,177.01)
  BOTTOM w0.152: R101.1 29.4,177.64 29.4,177.36 v1(29.75,177.01)
N19251792: length 2.6
  TOP w0.152: U8.5 v1(30.55,177.01)
  BOTTOM w0.152: v1(30.55,177.01) 30.51,177.05 R102.1
N19251796: length 2.9
  TOP w0.152: U8.4 v1(31.35,177.01)
  BOTTOM w0.152: R103.1 31.62,177.64 31.62,177.28 v1(31.35,177.01)
N19251798: length 2.9
  TOP w0.152: U8.2 v1(32.95,177.01)
  BOTTOM w0.152: v1(32.95,177.01) 33.21,177.26 33.21,177.64 R104.1
N19251812: length 2.9
  TOP w0.152: U8.8 v1(28.15,177.01)
  BOTTOM w0.152: v1(28.15,177.01) 27.81,177.35 27.81,177.64 R100.1
N19271739: length 2.6
  TOP w0.254: U1.41 v1(147.91,94.19)
  BOTTOM w0.508: v1(147.91,94.19) C24.1
N19272342: length 3
  TOP w0.254: U1.37 147.88,92.19 v1(148.08,92.39)
  BOTTOM w0.508: v1(148.08,92.39) 147.7,92.39 C24.2
N19279105: length 4.6
  TOP w0.301: C71.1 60.6,94.19 58.88,94.19 58.67,93.98 57.49,93.98 57.28,94.19 U2.41
N19280044: length 4.7
  TOP w0.301: U2.37 57.14,92.19 57.4,92.46 59.18,92.46 59.44,92.71 60.49,92.71 C71.2
N19304511: length 4.4
  TOP w0.508: C103.1 C104.1 ; C104.1 v1(146.43,37.69) ; C104.1 C102.1
  BOTTOM w0.762: U5.10 v1(146.43,37.69)
N19306537: length 4.4
  TOP w0.508: C108.1 C106.1 ; C108.1 C107.1 ; C108.1 142.49,37.81 v1(142.62,37.69)
  BOTTOM w0.762: U5.7 v1(142.62,37.69)
N19306786: length 4.5
  TOP w0.508: C110.1 C112.1 ; C112.1 138.68,37.81 v1(138.81,37.69) ; C112.1 C111.1
  BOTTOM w0.762: U5.4 v1(138.81,37.69)
N19307065: length 4.7
  TOP w0.508: v1(135,37.69) 134.75,37.94 C116.1 ; C115.1 C116.1 ; C116.1 C114.1
  BOTTOM w0.762: U5.1 v1(135,37.69)
N19311353: length 4.8
  TOP w0.508: C126.1 60.16,24.51 60.02,24.51 U6.12 58.97,25.6 ; 58.97,25.6 60.18,25.6 C125.1 ; 58.97,25.6 60.04,26.67 C124.1
N19311558: length 4.4
  TOP w0.152: 57.44,21.74 57.45,21.72 C128.1 ; C129.1 58.59,21.72 58.58,21.74
  TOP w0.508: 57.96,23.02 U6.6 57.44,22.59 57.44,21.74 ; 57.96,23.02 58.58,22.4 58.58,21.74 ; 57.96,23.02 C127.1
N19311775: length 4.3
  TOP w0.508: C130.1 47.71,23.02 ; 47.71,23.02 U6.1 48.29,22.52 C132.1 ; 47.71,23.02 47.18,22.49 C131.1
N19312774: length 5
  TOP w0.152: 45.44,24.35 45.41,24.32 C133.1 ; C135.1 45.44,26.51
  TOP w0.508: 45.44,26.51 45.83,26.51 U6.7 46.58,25.44 ; 46.58,25.44 46.58,25.11 45.82,24.35 45.44,24.35 ; 46.58,25.44 45.45,25.44 C134.1
N19315408: length 2.2
  TOP w0.762: C100.2 R35.1
N19315410: length 2.2
  TOP w0.762: R35.2 C101.1
N19317022: length 2.2
  TOP w0.762: C118.2 R60.1
N19317024: length 2.2
  TOP w0.762: R60.2 C119.1
N19317288: length 2.2
  TOP w0.762: C120.2 R61.1
N19317290: length 2.2
  TOP w0.762: R61.2 C121.1
N19317557: length 2.2
  TOP w0.762: R34.1 C98.2
N19317559: length 2.2
  TOP w0.762: C99.1 R34.2
N19395566: length 1.3
  BOTTOM w0.152: R23.2 C57.1
N19411569: length 1.4
  BOTTOM w0.508: Y4.1 77.98,83.18 R20.2
N19626709: length 68.6
  TOP w0.152: v1(148.3,93.34) 149.1,93.34 150.37,94.62 153.8,94.62 183.39,124.21 183.39,125.86 C23.1
  TOP w0.301: v1(148.3,93.34) 148.15,93.19 U1.39
  L4_PWR2 w0.914: TP29.1 182.67,94.32 ; TP29.1 181.06,95.93 ; TP29.1 182.67,95.93 ; TP29.1 181.06,94.32
  BOTTOM w0.508: v1(148.31,84.45) R9.1 v1(149.27,85.57)
N19642082: length 15.2
  TOP w0.152: R10.1 178.15,77.69 185.55,85.09 J6.1
N19649053: length 15.6
  TOP w0.152: R16.2 178.15,68.36 184.91,61.59 J7.1
N19710537: length 1.7
  BOTTOM w2.032: L18.2 JP47.2
N19710593: length 1.7
  BOTTOM w2.032: L19.2 JP48.2
N19712055: length 6.8
  TOP w0.152: J22.1 C194.2
N19732438: length 6
  TOP w0.152: C22.2 192.15,116.02 J4.1
N19876023: length 1.7
  BOTTOM w0.508: R119.1 JP35.1
N19879807: length 1.7
  BOTTOM w0.508: R121.1 JP37.1
N19880091: length 1.7
  BOTTOM w0.508: R122.1 JP38.1
N20143388: length 13.4
  TOP w0.152: U3.3 51.44,184.97 51.43,184.98 51.43,178.24
N20247366: length 18.5
  TOP w0.152: R139.2 52.93,130.78 59.82,137.67 J26.1
N20247420: length 19.2
  TOP w0.152: R137.2 32.44,130.99 39.12,137.67 J25.1
N20250415: length 22.3
  TOP w0.152: R136.2 v1(137.35,131.6)
  BOTTOM w0.152: J24.1 149.23,143.38 143.76,137.92 141.73,137.92 139.57,135.76 139.57,133.82 137.35,131.6 v1(137.35,131.6)
N20252579: length 13.3
  TOP w0.152: R138.2 112.27,139.22 J27.1
N20326527: length 6
  TOP w0.152: J5.1 192.15,135.57 192.16,135.57 C23.2
N20344726: length 5.6
  TOP w0.152: J3.1 C15.2
N20356781: length 5.6
  TOP w0.152: C156.2 J19.1
N20368817: length 7.5
  TOP w0.152: C203.2 105.12,73.28 J23.1
N20438631: length 1.6
  BOTTOM w0.152: R146.2 JP11.7
N20438658: length 1.6
  BOTTOM w0.152: R145.2 JP11.1
N20438885: length 1.6
  BOTTOM w0.152: R147.2 JP13.7
N20438965: length 1.6
  BOTTOM w0.152: R148.1 JP13.1
N20443701: length 1.7
  BOTTOM w0.152: R156.1 JP53.2
N20443710: length 1.7
  BOTTOM w0.152: R155.1 JP53.4
N20443719: length 1.7
  BOTTOM w0.152: R154.1 JP53.6
N20444304: length 1.7
  BOTTOM w0.152: R153.1 JP53.8
N20444313: length 1.7
  BOTTOM w0.152: R152.1 JP53.10
N20444322: length 1.7
  BOTTOM w0.152: R151.1 JP53.12
N20444660: length 4.9
  BOTTOM w0.152: R162.1 135.38,133.6 JP55.2
N20444664: length 4.8
  BOTTOM w0.152: R161.1 132.59,133.86 131.32,132.59 JP55.4
N20444668: length 4.8
  BOTTOM w0.152: R159.1 130.05,133.86 128.78,132.59 JP55.6
N20444672: length 4.8
  BOTTOM w0.152: JP55.8 126.24,132.59 127.51,133.86 R160.1
N20444676: length 4.8
  BOTTOM w0.152: R158.1 124.97,133.86 123.7,132.59 JP55.10
N20444680: length 4.8
  BOTTOM w0.152: JP55.12 121.16,132.59 122.43,133.86 R157.1
N20445311: length 10.9
  TOP w0.152: J28.1 87.63,52.07 85.72,50.17 R149.2
N20445323: length 7.3
  TOP w0.152: J29.1 9.4,59.35 R150.2
N20445616: length 2.3
  BOTTOM w0.152: R33.2 19.4,49.92 19.4,50.39 JP14.2
N20445860: length 10.6
  TOP w0.152: R164.2 26.71,54.14 29.72,57.15 J31.1
N20445926: length 9.4
  BOTTOM w0.152: JP54.2 21.46,52.45 17.14,52.45 16.38,51.69 R32.2
N20446666: length 9.9
  BOTTOM w0.152: JP56.2 100.97,37.21 96.65,32.89 R29.2
N20446778: length 8.5
  TOP w0.152: R163.2 J30.1
N171467441: length 5.5
  TOP w0.152: D4.2 10.66,45.55 v1(10.66,47.84)
  BOTTOM w0.152: R31.1 v1(10.66,47.84)
N171467701: length 2.3
  TOP w0.152: v1(89.53,34.13) D1.2
  BOTTOM w0.152: R28.1 v1(89.53,34.13)
N171468251: length 4
  TOP w0.152: D5.2 13.84,46.42 15.27,47.84 v1(15.28,47.84)
  BOTTOM w0.152: R32.1 v1(15.28,47.84)
N171469831: length 2.3
  TOP w0.152: v1(92.71,34.1) D2.2
  BOTTOM w0.152: v1(92.71,34.1) 92.8,34.01 R29.1
N192245170: length 3
  TOP w0.152: Q2.3 118.05,166.01 D10.2
N192245172: length 2.6
  TOP w0.152: Q2.1 121.47,167.82 121.82,167.48 122.73,167.48 v1(122.75,167.47)
  BOTTOM w0.152: v1(122.75,167.47) R127.2
N192284111: length 2.1
  TOP w0.508: Q1.3 D8.2
N192284251: length 3.6
  TOP w0.508: Q1.1 25.64,33.85 v1(27.81,33.85)
  BOTTOM w0.508: R112.2 v1(27.81,33.85)

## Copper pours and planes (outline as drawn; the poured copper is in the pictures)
GND on TOP (solid shape): 23.51,25.09 19.42,25.09 19.42,23.82 19.21,23.82 19.21,24.59 18.75,24.59 18.75,31.62 23.51,31.62
GND on TOP (solid shape): 124.33,174.62 118.48,174.62 118.48,178.72 117.21,178.72 117.21,178.92 117.98,178.92 117.98,179.39 124.33,179.39
GND on TOP (solid shape): 157.2,172.08 157.67,172.08 157.67,164.85 152.91,164.85 152.91,171.59 157,171.59 157,172.86 157.2,172.86
GND on TOP (solid shape): 177.52,174.62 177.99,174.62 177.99,167.39 173.23,167.39 173.23,174.13 177.32,174.13 177.32,175.4 177.52,175.4
GND on L2_GND, L5_GND: 5.59,17.27 5.59,163.58 10.67,163.58 10.67,176.4 40.13,176.4 40.13,188.47 78.99,188.47 78.99,176.4 99.57,176.4 99.57,195.33 149.1,195.33 149.1,203.45 198.88,203.45 198.88,28.45 118.11,28.45 118.11,17.27
GNDE on TOP (solid shape): outline of 401 points within 22.23,164.55 38.48,203.58
GNDE on TOP (solid shape): outline of 403 points within 80.64,164.55 96.9,203.45
GNDE on L2_GND, L5_GND: 1.02,1.02 1.02,203.45 147.83,203.45 147.83,196.22 98.3,196.22 98.3,177.55 79.76,177.55 79.76,189.23 38.86,189.23 38.86,177.29 10.16,177.29 10.16,164.34 4.32,164.34 4.32,15.49 119.38,15.49 119.38,26.67 198.88,26.67 198.88,1.02
GNDE on L3_PWR1: 2.79,26.67 2.79,1.02 198.12,1.02 198.12,26.67
GNDE on L4_PWR2: 198.88,19.05 198.88,1.02 2.54,1.02 2.54,19.05
VCC_3.3V on TOP (solid shape): 172.59,164.94 168.15,164.94 168.15,173.67 172.59,173.67
VCC_3.3V on L4_PWR2: 2.54,202.95 198.63,202.95 198.63,164.59 9.91,164.59 9.91,62.48 15.25,62.48 15.25,45.21 15.24,45.13 15.24,33.02 2.54,33.02
VCC_5V on L3_PWR1: 2.41,201.42 2.41,27.43 16.51,27.43 16.51,49.78 13.21,49.78 13.21,188.47 117.09,188.47 117.09,184.66 162.81,184.66 162.81,166.88 197.36,166.88 197.36,201.42
VDD_1.0V on TOP (solid shape): 126.87,169.54 118.94,169.54 118.94,173.99 126.87,173.99
GEN_VDDO on TOP (solid shape): 152.27,164.47 144.65,164.47 144.65,171.13 152.27,171.13
GEN_VDDO on L3_PWR1: 173.86,95.5 173.86,166.37 162.31,166.37 162.31,183.64 116.08,183.64 116.08,187.45 13.97,187.45 13.97,52.32 91.95,52.32 91.95,44.45 96.77,44.45 96.77,88.39 103.12,88.39 103.12,109.73 80.52,109.73 80.52,91.44 83.06,91.44 83.06,57.4 69.6,57.4 69.6,64.01 25.27,64.01 25.27,151.89 47.62,151.89 47.62,161.8 106.68,161.8 106.68,170.69 144.78,170.69 144.78,97.03 154.94,97.03 154.94,95.5
U1_1.8V on L3_PWR1: 166.62,44.96 166.62,35.05 132.84,35.05 132.84,29.97 122.94,29.97 122.94,44.96
U1_AVDD_1.8V on L4_PWR2: 137.41,90.17 144.53,90.17 144.53,92.84 147.07,92.84 147.07,82.93 189.99,82.93 189.99,35.56 137.41,35.56
U1_AVDD_3.3V on L3_PWR1: 137.67,87.63 98.04,87.63 98.04,45.72 144.53,45.72 144.53,88.9 137.67,88.9
U1_AVDDC_1.8V on L3_PWR1: 144.53,91.44 147.32,91.44 147.32,90.42 152.65,90.42 152.65,88.14 169.16,88.14 169.16,46.23 145.29,46.23 145.29,89.66 144.53,89.66
U1_AVDDF_1.8V on L4_PWR2: 115.57,97.16 115.57,46.36 136.91,46.36 136.91,93.22 139.45,93.22 139.45,97.16
U1_VDD_1.0V on L4_PWR2: 115.57,155.19 159.51,155.19 159.51,95.63 148.59,95.63 148.59,94.74 147.32,94.74 147.32,93.34 144.02,93.34 144.02,90.68 137.41,90.68 137.41,92.71 139.95,92.71 139.95,97.66 115.57,97.66
U1_VDD_3.3V on L3_PWR1: 147.83,90.93 153.16,90.93 153.16,88.65 185.93,88.65 185.93,113.28 176.02,113.28 176.02,95 154.18,95 154.18,96.52 144.78,96.52 144.78,91.95 147.83,91.95
U1_VDDO on L3_PWR1: 99.06,110.49 99.06,119.63 144.27,119.63 144.27,92.2 142.24,92.2 142.24,89.41 136.91,89.41 136.91,88.39 103.89,88.39 103.89,110.49
U2_1.8V on L3_PWR1: 91.31,28.96 17.78,28.96 17.78,51.56 91.31,51.56
U2_AVDD_1.8V on L4_PWR2: 46.23,49.53 46.23,88.9 55.12,88.9 55.12,92.96 56.9,92.96 56.9,93.98 77.98,93.98 77.98,49.53
U2_AVDD_3.3V on L3_PWR1: 25.91,64.77 25.91,88.65 54.61,88.65 54.61,64.77
U2_AVDDC_1.8V on L3_PWR1: 55.24,91.69 55.24,64.77 70.36,64.77 70.36,57.91 82.42,57.91 82.42,90.81 59.18,90.81 59.18,91.69
U2_AVDDF_1.8V on L4_PWR2: 28.7,42.42 45.59,42.42 45.59,93.34 50.04,93.34 50.04,100.33 28.7,100.33
U2_VDD_1.0V on L4_PWR2: 38.1,149.1 77.98,149.1 77.98,94.49 56.39,94.49 56.39,93.47 54.48,93.47 54.48,89.54 46.23,89.54 46.23,92.71 50.55,92.71 50.55,100.84 38.1,100.84
U2_VDD_3.3V on L3_PWR1: 55.24,113.03 55.24,92.71 59.69,92.71 59.69,91.44 79.88,91.44 79.88,113.03
U2_VDDO on L3_PWR1: 25.91,89.15 25.91,113.03 54.61,113.03 54.61,89.15
N19224300 on L4_PWR2: 78.49,49.53 113.03,49.53 113.03,136.7 113.02,136.7 113.02,155.96 160.27,155.96 160.27,106.68 198.12,106.68 198.12,164.08 10.41,164.08 10.41,63.25 28.19,63.25 28.19,100.84 37.59,100.84 37.59,149.61 78.49,149.61
N19224342 on TOP (solid shape): 124.33,180.02 117.9,180.02 117.9,179.73 117.26,179.73 117.26,184.78 124.33,184.78
N19224390 on TOP (solid shape): 183.39,168.27 178.63,168.27 178.63,174.71 178.34,174.71 178.34,175.35 183.39,175.35
N19224677 on TOP (solid shape): 117.73,179.21 116.9,179.21 116.9,178.46 117.86,178.46 117.86,169.54 112.27,169.54 112.27,175.77 117.27,175.77 117.27,178.19 116.55,178.19 116.55,179.44 117.73,179.44
N19224758 on L3_PWR1: 48.13,151.89 48.13,161.29 107.19,161.29 107.19,170.18 137.92,170.18 137.92,151.89
N19224948 on TOP (solid shape): 174.37,175.34 176.8,175.34 176.8,176.06 178.04,176.06 178.04,174.88 177.81,174.88 177.81,175.7 177.06,175.7 177.06,174.75 168.15,174.75 168.15,180.34 174.37,180.34
N19227820 on L3_PWR1: 98.55,113.79 25.91,113.79 25.91,151.38 138.68,151.38 138.68,167.89 138.94,168.15 144.27,168.15 144.27,120.14 98.55,120.14
N19228189 on TOP (solid shape): 163.07,165.73 158.31,165.73 158.31,172.17 158.02,172.17 158.02,172.81 163.07,172.81
N19228243 on TOP (solid shape): 18.11,24.51 18.4,24.51 18.4,23.87 13.35,23.87 13.35,30.94 18.11,30.94
N19228347 on TOP (solid shape): 28.59,25.54 24.14,25.54 24.14,31.62 28.59,31.62
N19228465 on TOP (solid shape): 28.59,18.88 22.37,18.88 22.37,23.88 19.94,23.88 19.94,23.16 18.69,23.16 18.69,24.34 18.92,24.34 18.92,23.51 19.67,23.51 19.67,24.46 28.59,24.46
N19228834 on TOP (solid shape): 154.05,172.8 156.48,172.8 156.48,173.52 157.72,173.52 157.72,172.34 157.49,172.34 157.49,173.16 156.74,173.16 156.74,172.21 147.83,172.21 147.83,177.8 154.05,177.8
N19228961 on L4_PWR2: 28.7,37.34 128.02,37.34 128.02,24.89 28.7,24.89
N19626709 on L4_PWR2: 147.83,83.82 184.15,83.82 184.15,97.03 175.01,97.03 175.01,94.74 149.61,94.74 149.61,93.73 147.83,93.73

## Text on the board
BOTTOM: 88E1512/88E1512P QFN56 SVB | MV-L201097-00 Rev 1.1
Ref Des/Silkscreen Top: U2_SOUTN | U2_SINN | U2_CF | U2_SOUTP | U2_SINP | U2_V18 | U2_AVDD33 | GND | U2_TX_CLK | RESET | U1_SOUTN | U2_RX_CLK | U1_SOUTP | U2_VDD33 | TSTPT | En | U2_25_CLK_IN | U1_SINN | U1_AVDD33_NOISE_IN | U1_CF | U1_AVDD33 | U1_VDDO | U1_SINP | U1_V18 | U1_TX_CLK | VDD1.0V | MDIO | MDC | U1_RX_CLK | GEN_VDDO | U1_VDD10 | VCC3.3V | U1_VDD33_NOISE_IN | U1_AVDD18_NOISE_IN | U1_VDD33 | - | HSDAC+ | HSDAC- | U1_25_CLK_IN | U1_AVDDL | 00 | 01 | 10 | 11 | LED2 | U2_LED1 | U2_VDDO | U2_AVDDF_1.8V | U2TX_CLK | TX3 | TX2 | TX1 | TX0 | TX_CTRL | U2_VDD_1.0V | RX3 | RX2 | RX1 | RX0 | RX_CTRL | U2_AVDD_1.8V | HPDAC | + | U2_AVDDC_1.8V | U1_LED1 | U1_AVDDF_1.8V | U1_VDD_1.0V | TX_CTR | U1RX_CLK | RX_CRTL | 3.3 | U1_AVDD_1.8V | 2.5 | 1.8 | 1.5 | U1_AVDDC_1.8V | HSDAC | U2_PTP_CLK | U2_CLK125 | U2_TRIG_GEN | U2 | G | U1 | U1_PTP_CLK | U1_CLK125 | U1_TRIG_GEN | 5V | LED0 | LED1 | U2_1.8V | ALL_U1_1.8V | REV | S/N | 88E1512/88E1512P QFN56 SVB | MV-L201097-10 | MARVELL SEMICONDUCTOR
User.17: FIGURE | SIZE | 12.0 | 34.0 | 35.0 | 40.0 | 45.0 | 52.0 | 55.0 | 58.0 | 62.0 | 67.0 | 125.0 | 37.0 | 61.0 | 63.0 | 73.0 | 128.0 | 270.0 | DRILL CHART: TOP to BOTTOM | ALL UNITS ARE IN MILS | TOLERANCE | +3.0/-3.0 | +4.0/-4.0 | +2.0/-2.0 | PLATED | NON-PLATED | QTY | 643 | 2 | 38 | 222 | 4 | 20 | 80 | 8 | 18
User.18: .005/.012
